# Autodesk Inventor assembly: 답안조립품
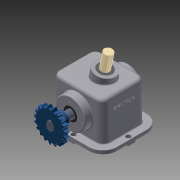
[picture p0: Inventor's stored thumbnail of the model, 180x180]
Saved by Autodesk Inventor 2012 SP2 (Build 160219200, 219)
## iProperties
Created: 2014-11
Part Number: 답안조립품
Document SubType Name: Assembly
Designer: cad-man
Author: cad-man
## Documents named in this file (13)
- C:\Users\cad-man\Desktop\강창규-441123V1021\답안조립품.iam
- C:\Users\cad-man\Desktop\강창규-441123V1021\본체.ipt
- C:\Users\cad-man\Desktop\강창규-441123V1021\뒤커버.ipt
- C:\Users\cad-man\Desktop\강창규-441123V1021\앞커버.ipt
- C:\Users\cad-man\Desktop\강창규-441123V1021\M4x0.5.ipt
- C:\Users\cad-man\Desktop\강창규-441123V1021\베어링 6205.ipt
- C:\Users\cad-man\Desktop\강창규-441123V1021\부시.ipt
- C:\Users\cad-man\Desktop\강창규-441123V1021\오일실.ipt
- C:\Users\cad-man\Desktop\강창규-441123V1021\편심축.ipt
- C:\Users\cad-man\Desktop\강창규-441123V1021\키 8x8.ipt
- C:\Users\cad-man\Desktop\강창규-441123V1021\5-체인 스프로킷.ipt
- C:\Users\cad-man\Desktop\강창규-441123V1021\멈춤나사 M5x0.5.ipt
- C:\Users\cad-man\Desktop\강창규-441123V1021\슬라이드.ipt
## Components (9 placed, 2 different names)
1. M4x0.5:1
2. M4x0.5:2
3. M4x0.5:3
4. M4x0.5:4
5. M4x0.5:5
6. M4x0.5:6
7. M4x0.5:7
8. M4x0.5:8
9. 5-체인 스프로킷:1
